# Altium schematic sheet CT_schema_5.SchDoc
size 385 x 355 mm
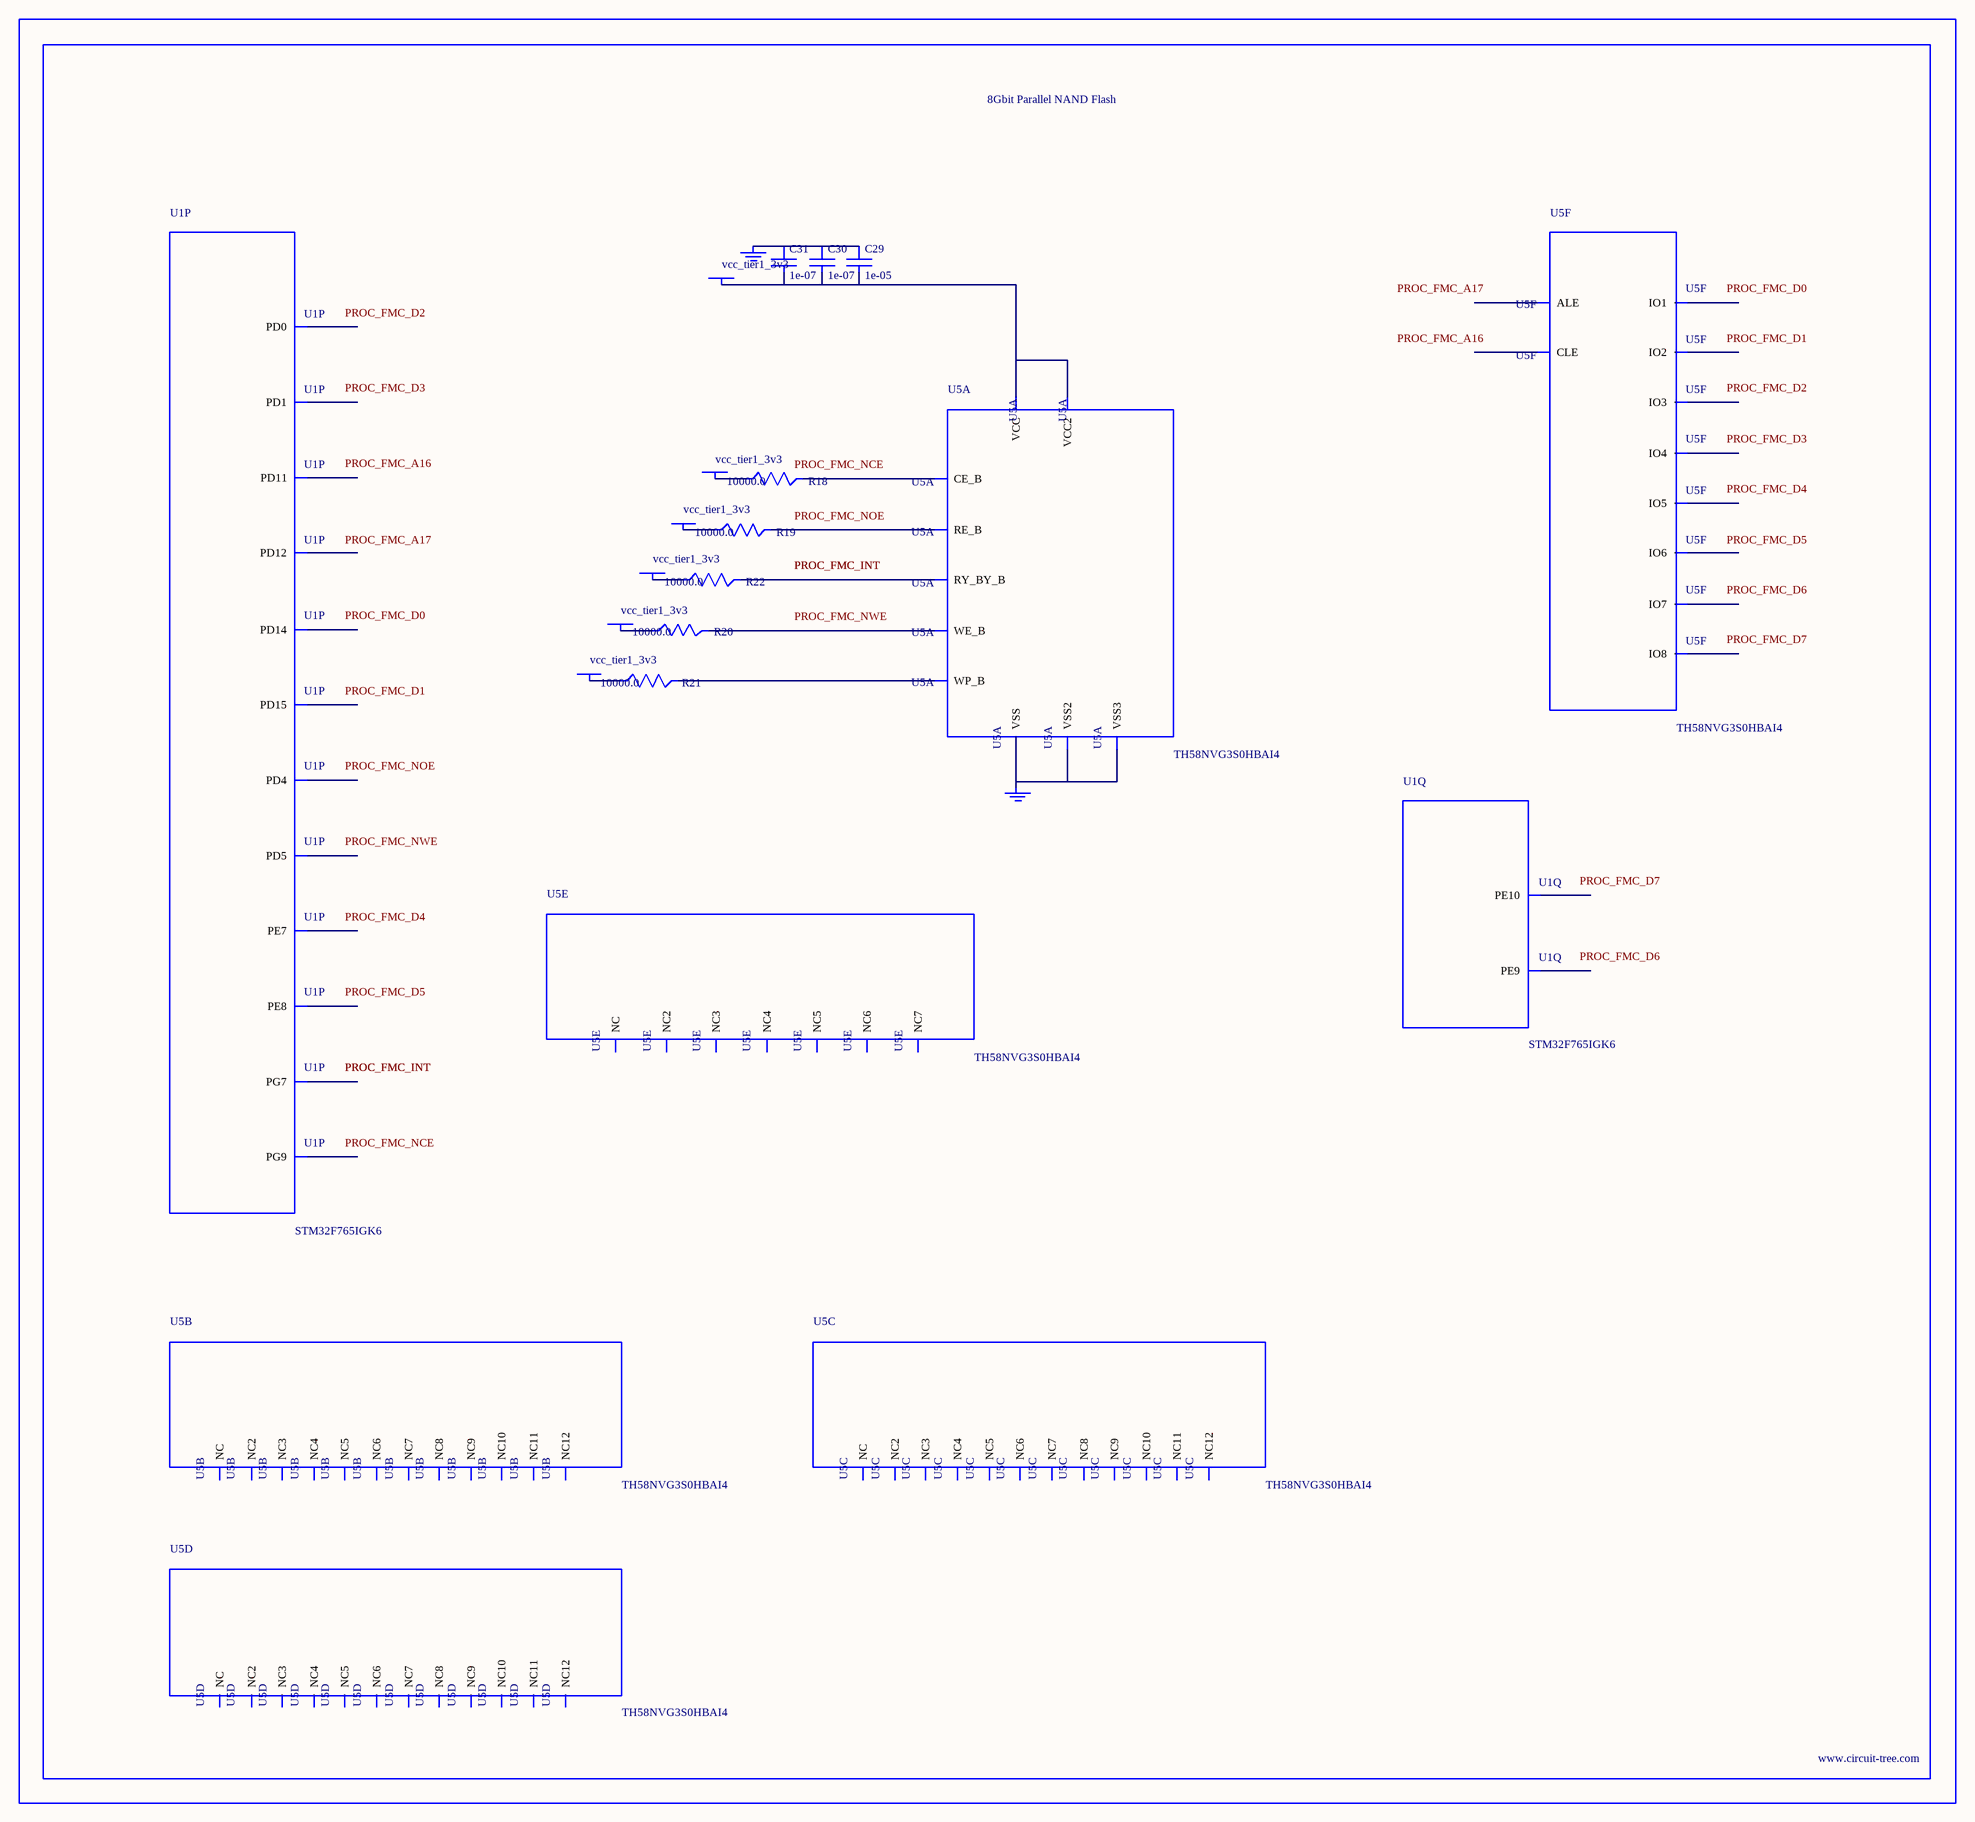
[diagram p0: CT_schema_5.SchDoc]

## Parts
BORDER4  (no value)
C29  1e-05  [C0805]
C30  1e-07  [C0402]
C31  1e-07  [C0402]
GND_INSTANCE_4_0  (no value)
GND_INSTANCE_4_1  (no value)
POWER_INSTANCE_4_0  vcc_tier1_3v3
POWER_INSTANCE_4_1  vcc_tier1_3v3
POWER_INSTANCE_4_2  vcc_tier1_3v3
POWER_INSTANCE_4_3  vcc_tier1_3v3
POWER_INSTANCE_4_4  vcc_tier1_3v3
POWER_INSTANCE_4_5  vcc_tier1_3v3
R18  10000.0  [R0603]
R19  10000.0  [R0603]
R20  10000.0  [R0603]
R21  10000.0  [R0603]
R22  10000.0  [R0603]
U1  STM32F765IGK6  [UFBGA176_25]  (parts P,Q of 17)
U5  TH58NVG3S0HBAI4  [TH58NVG3S0HBAI4]  (parts A,B,C,D,E,F of 6)

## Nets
NetC29_1: C29.1 C30.1 C31.1 GND_INSTANCE_4_0.0(GND)
NetC29_2: C29.2 C30.2 C31.2 POWER_INSTANCE_4_5.0(PWR) U5.H8(VCC) U5.J6(VCC2)
NetGND_INSTANCE_4_1_0: GND_INSTANCE_4_1.0(GND) U5.C5(VSS) U5.K3(VSS2) U5.K8(VSS3)
NetPOWER_INSTANCE_4_0_0: POWER_INSTANCE_4_0.0(PWR) R18.1
NetPOWER_INSTANCE_4_1_0: POWER_INSTANCE_4_1.0(PWR) R19.1
NetPOWER_INSTANCE_4_2_0: POWER_INSTANCE_4_2.0(PWR) R20.1
NetPOWER_INSTANCE_4_3_0: POWER_INSTANCE_4_3.0(PWR) R21.1
NetPOWER_INSTANCE_4_4_0: POWER_INSTANCE_4_4.0(PWR) R22.1
NetR18_2: R18.2 U5.C6(CE_B)
NetR19_2: R19.2 U5.D4(RE_B)
NetR20_2: R20.2 U5.C7(WE_B)
NetR21_2: R21.2 U5.C3(WP_B)
NetR22_2: R22.2 U5.C8(RY_BY_B)

Not connected (* = marked no-connect by the designer): U1 B12(PD0) C10(PG9) C11(PD5) C12(PD1) D10(PD4) J14(PG7) L14(PD15) M14(PD14) N13(PD12) N14(PD11) P8(PE8) P9(PE9) R8(PE7) R9(PE10); U5 A1(NC) A2(NC3) A9(NC4) A10(NC2) B1(NC5) B9(NC7) B10(NC6) C4(ALE) D3(NC8) D5(CLE) D6(NC9) D7(NC10) D8(NC11) E3(NC12) E4(NC) E5(NC2) E6(NC3) E7(NC4) E8(NC5) F3(NC6) F4(NC7) F5(NC8) F6(NC9) F7(NC10) F8(NC11) G3(NC12) G4(NC) G5(NC2) G6(NC3) G7(NC4) G8(NC5) H3(NC6) H4(IO1) H5(NC7) H6(NC8) H7(NC9) J3(NC10) J4(IO2) J5(NC11) J7(IO6) J8(IO8) K4(IO3) K5(IO4) K6(IO5) K7(IO7) L1(NC12) L2(NC2) L9(NC3) L10(NC) M1(NC4) M2(NC6) M9(NC7) M10(NC5)

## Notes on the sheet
- Labels drawn without touching a wire or pin: PROC_FMC_A16, PROC_FMC_A17, PROC_FMC_D0, PROC_FMC_D1, PROC_FMC_D2, PROC_FMC_D3, PROC_FMC_D4, PROC_FMC_D5, PROC_FMC_D6, PROC_FMC_D7, PROC_FMC_NCE, PROC_FMC_NOE, PROC_FMC_NWE

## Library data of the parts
BORDER4 = BORDER_PAGE4
C29 = C0805C106K8RACTU
C30 C31 = C0402C104K3RACTU
GND_INSTANCE_4_0 GND_INSTANCE_4_1 = GND
POWER_INSTANCE_4_0-POWER_INSTANCE_4_5 = PWR
R18-R22 = RC0603JR-0710KL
